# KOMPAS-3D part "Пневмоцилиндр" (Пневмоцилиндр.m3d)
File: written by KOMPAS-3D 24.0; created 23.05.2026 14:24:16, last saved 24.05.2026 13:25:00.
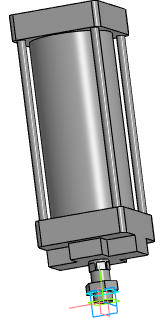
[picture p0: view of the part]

Document properties: Автор: R2D2; Полное имя файла: E:\Работа\Зайцев\GVKR1331E-1W-Fb-2P Задвижка шиберная DN.ru Ду50-300 Ру16-10-6\исходные материалы\DN250\Пневмоцилиндр.m3d

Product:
- Part/product: Пневмоцилиндр
    Масса: 88.034437

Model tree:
1. Эскиз:1
2. Элемент выдавливания:1
3. Смещенная плоскость:1
4. Эскиз:2
5. Элемент выдавливания:2
6. Эскиз:3  (with: Грань.Элемент выдавливания:1)
7. Элемент выдавливания:3
8. Эскиз:4  (with: Грань.Элемент выдавливания:3)
9. Элемент выдавливания:4  (with: Грань.Элемент выдавливания:3)
     Расстояние 2 = 15; Смещение 2 = 5
10. Эскиз:5  (with: Грань.Элемент выдавливания:3)
11. Элемент выдавливания:5
12. Эскиз:6  (with: Грань.Элемент выдавливания:5)
13. Элемент выдавливания:6
14. Эскиз:7  (with: Грань.Элемент выдавливания:6)
15. Элемент выдавливания:7
16. Эскиз:8  (with: Грань.Элемент выдавливания:7, Ребро.Элемент выдавливания:6)
17. Элемент выдавливания:8
18. Эскиз:9  (with: Грань.Элемент выдавливания:6, Вершина.Элемент выдавливания:8)
19. Элемент выдавливания:9  (with: Грань.Элемент выдавливания:8)
     Расстояние 1 = 351
20. Массив по концентрической сетке:1  (with: Элемент выдавливания:9, Эскиз:9)  (4 pattern instances)
     Шаг 2 = 360
21. Скругление:1  (with: Ребро.Элемент выдавливания:6, Ребро.Элемент выдавливания:8)
     Радиус = 10
22. Эскиз:10  (with: Грань.Элемент выдавливания:5, Ребро.Элемент выдавливания:6, Ребро.Элемент выдавливания:8)
23. Элемент выдавливания:10
24. Эскиз:11  (with: Грань.Элемент выдавливания:5, Ребро.Элемент выдавливания:10)
25. Элемент выдавливания:11
26. Эскиз:12  (with: Ребро.Элемент выдавливания:6, Ребро.Элемент выдавливания:5)
27. Элемент выдавливания:12

Expressions: k/2; c-2*g+x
